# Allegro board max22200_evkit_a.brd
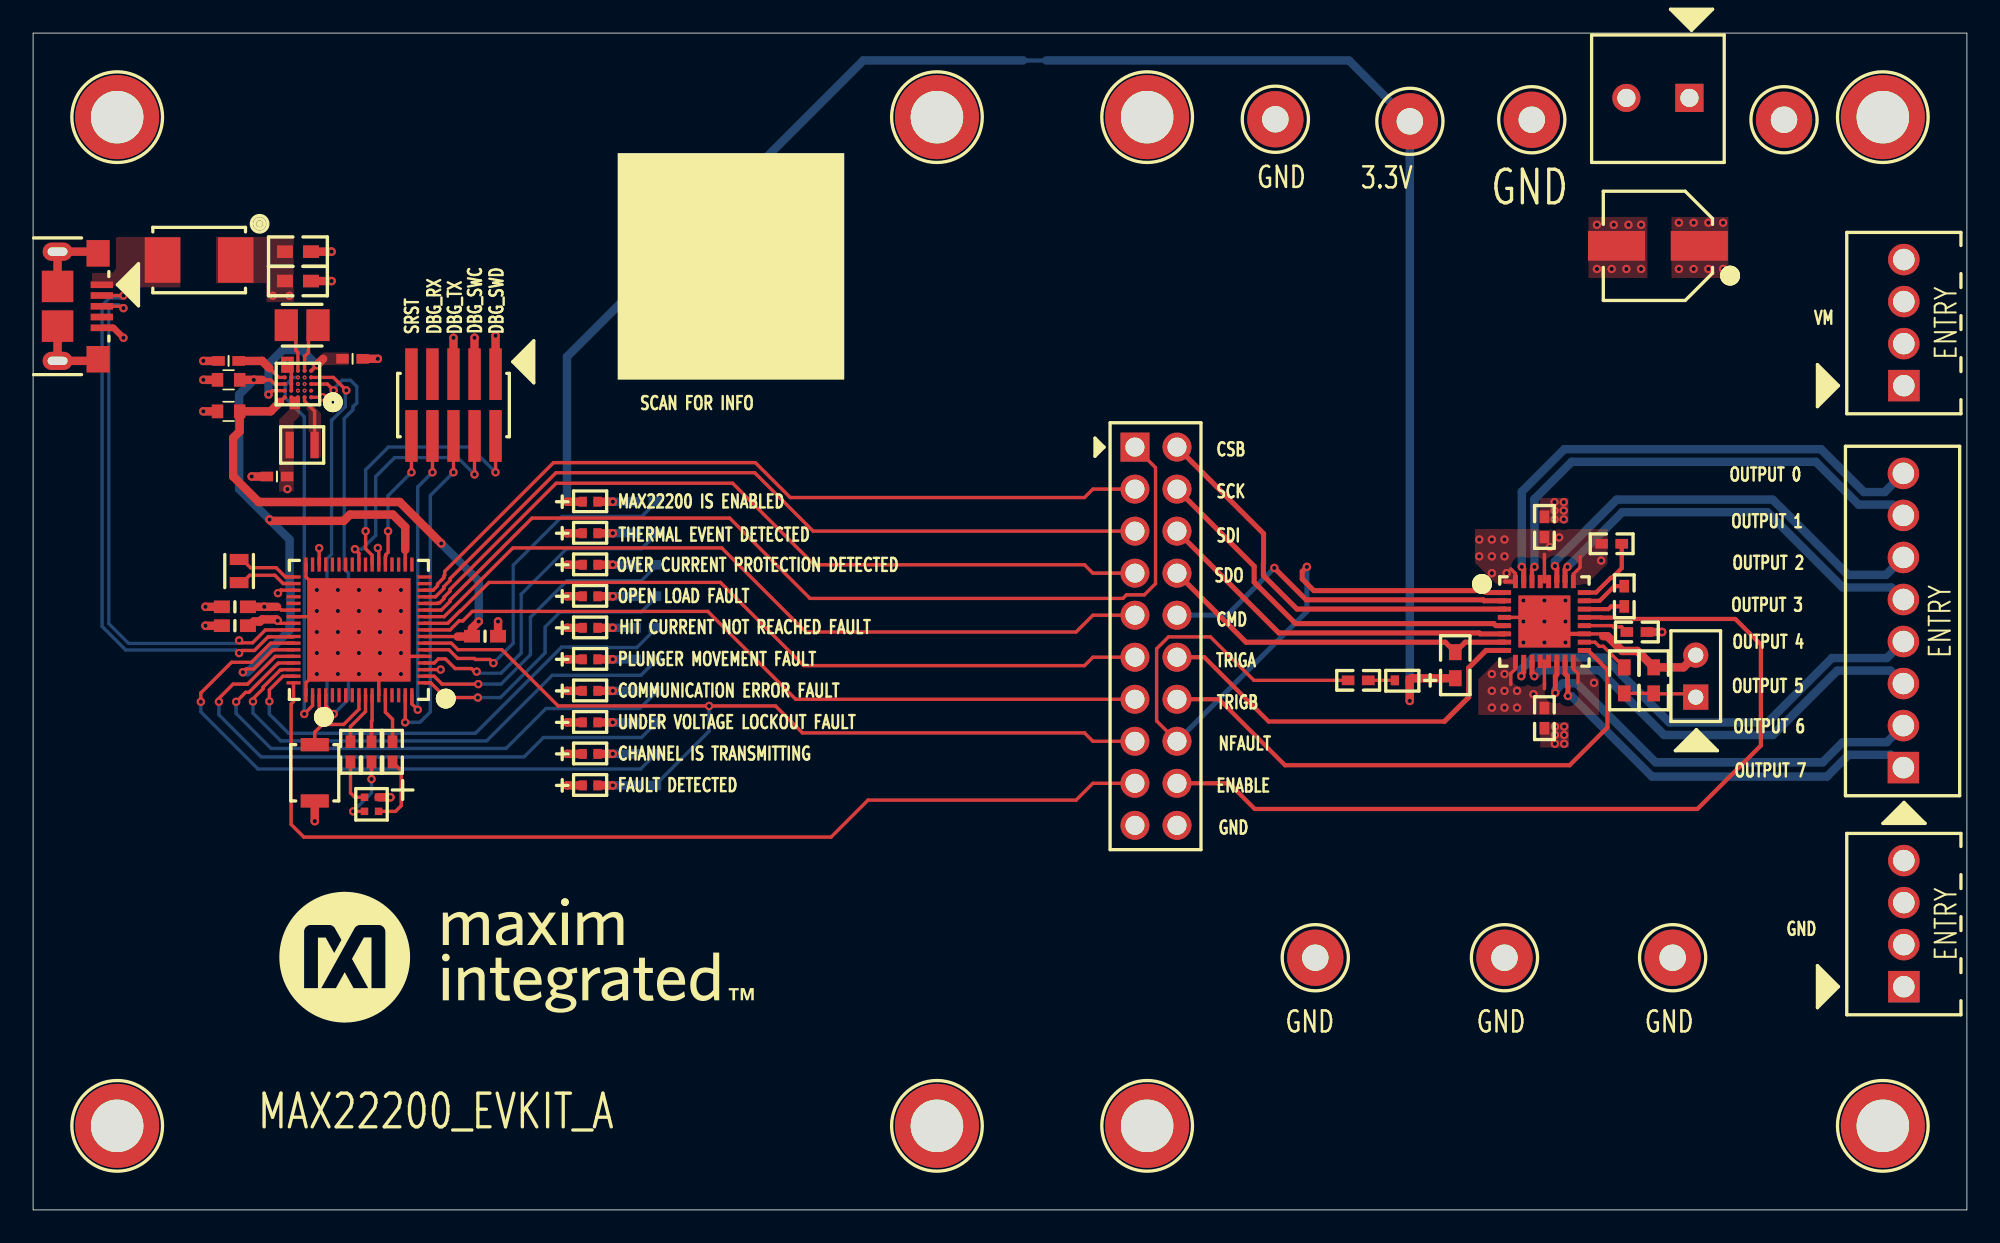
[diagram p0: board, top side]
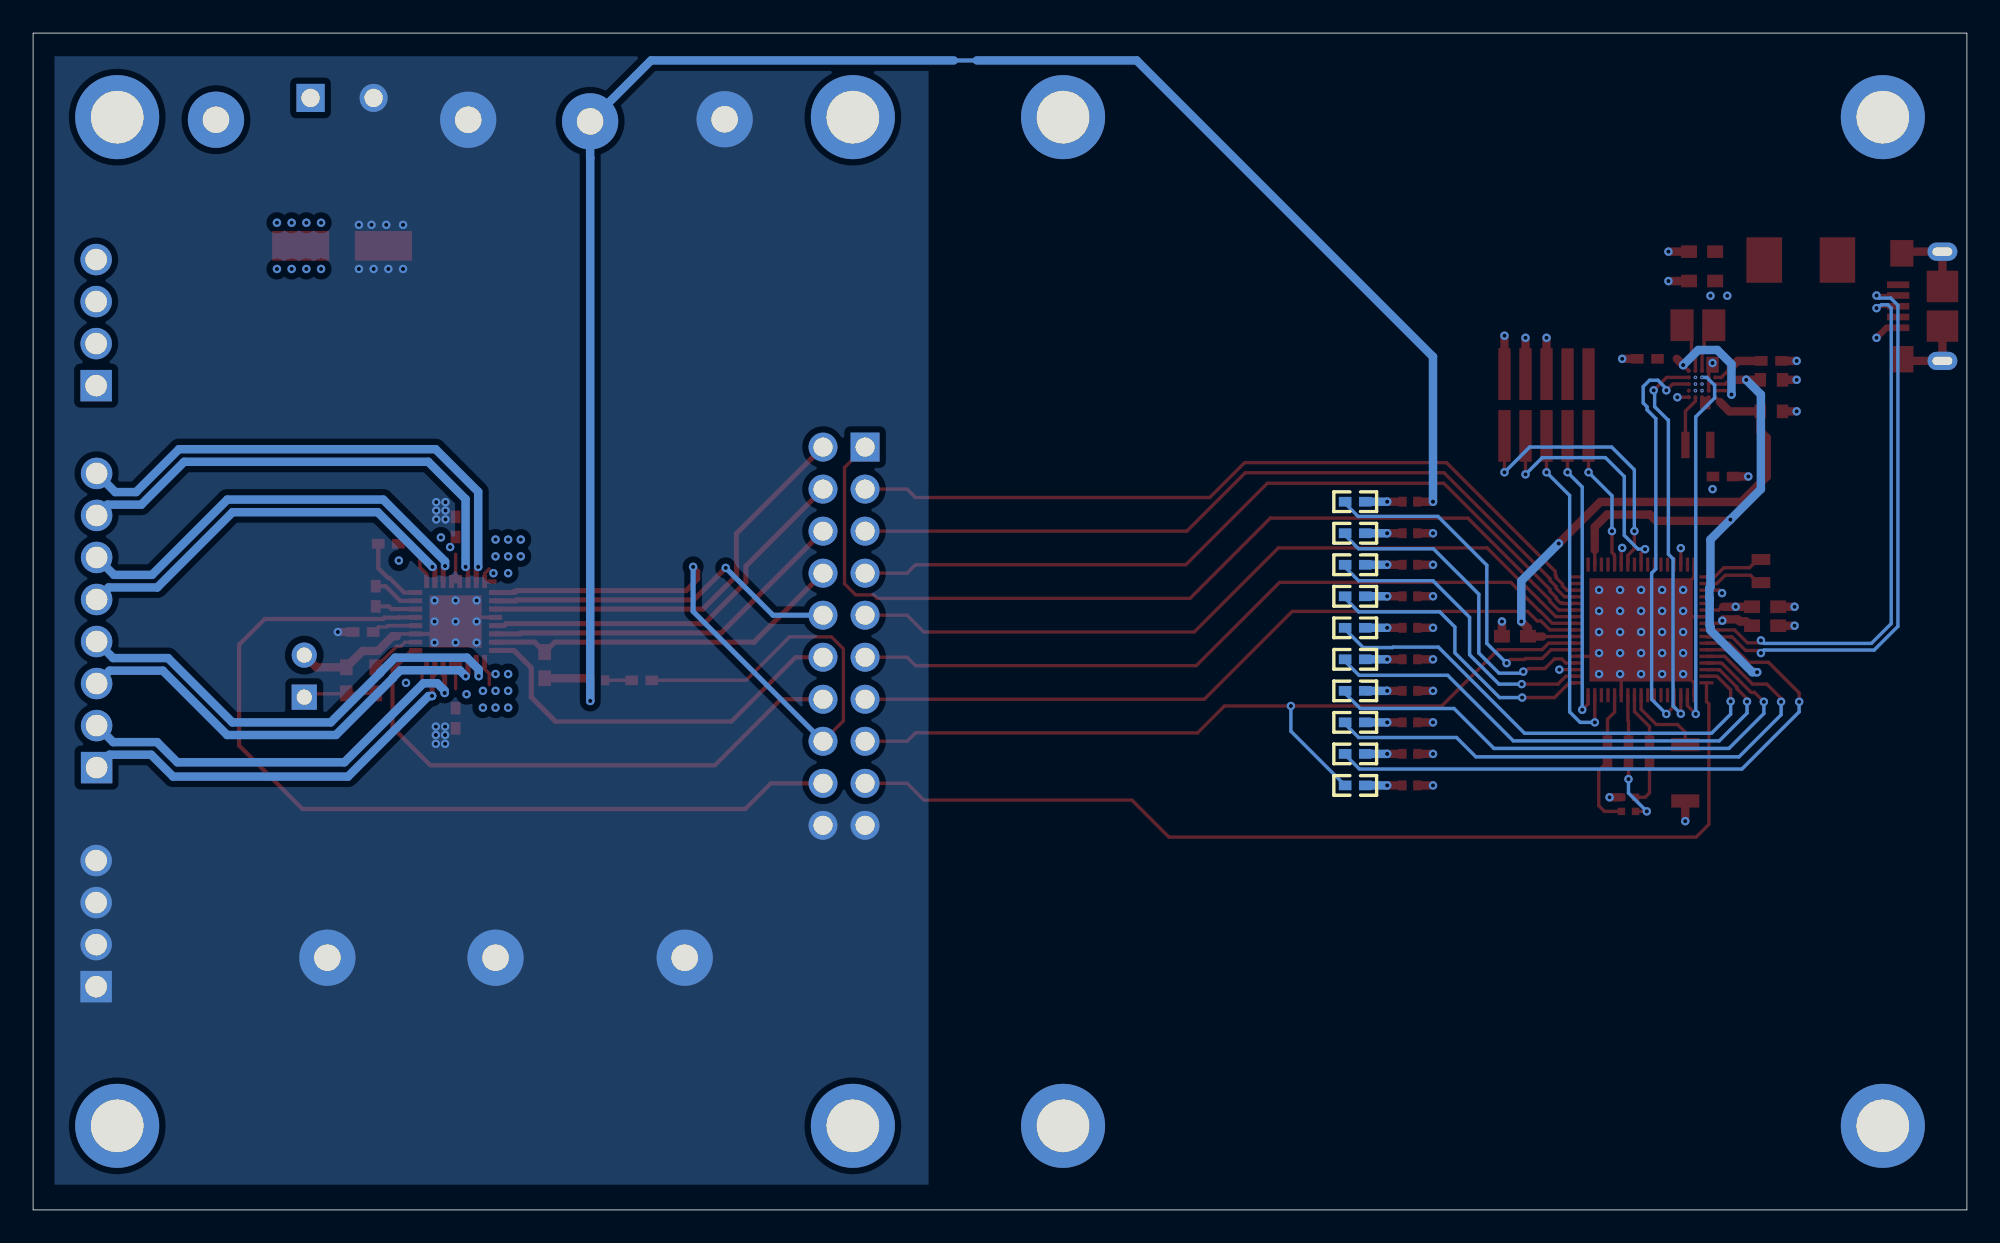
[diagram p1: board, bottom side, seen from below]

Outline 116.84 x 71.12 mm; copper layers: TOP, GND2, PWR3, BOTTOM. Coordinates in mm from the lower left corner of the outline.
Outline path: 0,71.12 116.84,71.12 116.84,0 0,0 0,71.12

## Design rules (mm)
constraint set DEFAULT: min track width 0.203
net group DIFF_USB: nets USB_DM USB_DP
net group PWR_DRIVER: nets UNNAMED_1_EKMAX22200_I141_10 UNNAMED_1_EKMAX22200_I141_11 UNNAMED_1_EKMAX22200_I141_14 UNNAMED_1_EKMAX22200_I141_15 UNNAMED_1_EKMAX22200_I141_26 UNNAMED_1_EKMAX22200_I141_27 UNNAMED_1_EKMAX22200_I141_30 UNNAMED_1_EKMAX22200_I141_31 VDD

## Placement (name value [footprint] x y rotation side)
C1  1UF  [0603#2]  16 56.13 180 top
C2  10UF  [0603#2]  16 57.91 180 top
C3  22UF  [0402]  19.3 51.44 0 top
C4  22UF  [0402]  14.73 44.32 0 top
C5  10UF  [0603]  11.81 48.26 0 top
C6  1UF  [0603]  11.81 50.16 0 top
C7  0.1UF  [0402]  11.81 51.31 180 top
C8  1UF  [0603#2]  12.19 35.31 0 top
C9  1UF  [0603#2]  27.3 34.67 180 top
C10  1UF  [0603#2]  12.19 36.45 0 top
C17  0.22UF  [0402]  91.31 41.27 90 top
C18  0.22UF  [0402]  91.31 29.72 270 top
C19  2.2UF  [0402]  96.9 34.92 180 top
C20  1UF  [0402]  95.38 40.26 180 top
C21  0.022UF  [0402]  96.14 37.08 90 top
C23  22UF  [CAPAE660X580M]  98.17 58.26 180 top
D1  SML-P11MTT86  [LED_0402]  33.66 42.8 180 top
D2  SML-P11UTT86  [LED_0402]  33.66 40.89 180 top
D3  SML-P11UTT86  [LED_0402]  33.66 38.99 180 top
D4  SML-P11UTT86  [LED_0402]  33.66 37.08 180 top
D5  SML-P11UTT86  [LED_0402]  33.66 35.18 180 top
D6  SML-P11UTT86  [LED_0402]  33.66 33.27 180 top
D7  SML-P11UTT86  [LED_0402]  33.66 31.37 180 top
D8  SML-P11UTT86  [LED_0402]  33.66 29.46 180 top
D9  SML-P11MTT86  [LED_0402]  33.66 27.56 180 top
D10  SML-P11UTT86  [LED_0402]  33.66 25.65 180 top
D11  VS-10BQ040-M3  [DIOM5436X265M]  10.03 57.4 180 top
D12  SML-LX0404SIUPGUSB  [LED_LX0404]  20.45 24.51 0 top
D13  SML-P11UTT86  [LED_0402]  82.73 32 0 top
J1  10118193-0001LF  [FCI_10118193-0001LF]  1.48 54.61 270 top
J2  FTS-105-01-L-DV  [EK_SAMTEC_FTS-105-01-L-DV]  25.4 48.64 180 top
J3  N/A  [KEYS_5010]  83.19 65.79 0 top
J4  1727010  [PNIX_1727010]  100.08 67.2 180 top
J6  N/A  [KEYS_5010]  105.79 65.88 0 top
J7  N/A  [KEYS_5011]  90.55 65.88 0 top
J8  N/A  [KEYS_5011]  75.06 65.91 0 top
J9  OSTVN04A150  [OSTI_OSTVN04A1X0]  113.03 49.81 90 top
J10  OSTVN04A150  [OSTI_OSTVN04A1X0]  113.03 13.49 90 top
J11  PEC10DAAN  [SULLINS_PXC10DAAN]  66.57 46.1 270 top
J12  OSTVN08A150  [OST_OSTVN08A1X0]  113 26.73 90 top
J13  N/A  [KEYS_5011]  77.47 15.24 0 top
J14  N/A  [KEYS_5011]  88.9 15.24 0 top
J15  N/A  [KEYS_5011]  99.06 15.24 0 top
J16  PBC02SAAN  [EK_SULLINS_PXC02SAAN]  100.46 30.99 90 top
L1  2.2UH  [IND_VLS-HBX-1]  16.26 46.23 180 top
L2  4.7UH  [INDC2016X120M]  16.26 53.47 180 top
NOREF  -  []  35.32 50.18 0 top
NOREF#2  -  [unnamed#2]  111.76 66.04 0 top
NOREF#3  -  []  58.36 100.35 0 top
NOREF#4  -  []  123.19 141.32 0 top
NOREF#5  -  []  0 8.89 90 top
NOREF#6  -  []  91.12 143.29 0 top
NOREF#7  -  []  2.35 16.47 0 top
NOREF#8  -  []  0 71.12 0 top
NOREF#9  -  []  18.85 15.17 0 top
NOREF#10  -  []  161.29 25.4 0 top
NOREF#11  -  [unnamed#2]  67.31 5.08 0 top
NOREF#12  -  []  51.73 10.79 0 top
NOREF#13  -  []  12.7 -12.7 0 top
NOREF#14  -  [unnamed#2]  54.61 66.04 0 top
NOREF#15  -  [unnamed#2]  67.31 66.04 0 top
NOREF#16  -  [unnamed#2]  54.61 5.08 0 top
NOREF#17  -  [unnamed#2]  5.08 66.04 0 top
NOREF#18  -  []  93.34 85.09 0 top
NOREF#19  -  [unnamed#2]  111.76 5.08 0 top
NOREF#20  -  [unnamed#2]  5.08 5.08 0 top
R1  3.09K  [0402]  21.72 27.69 270 top
R2  1.1K  [0402]  20.45 27.69 270 top
R3  1.4K  [0402]  19.18 27.69 270 top
R5  1.5K  [0402]  36.96 42.8 0 bottom
R6  1.4K  [0402]  36.96 40.89 0 bottom
R7  1.4K  [0402]  36.96 38.99 0 bottom
R8  1.4K  [0402]  36.96 37.08 0 bottom
R9  1.4K  [0402]  36.96 35.18 0 bottom
R10  1.4K  [0402]  36.96 33.27 0 bottom
R11  1.4K  [0402]  36.96 31.37 0 bottom
R12  1.4K  [0402]  36.96 29.46 0 bottom
R13  1.5K  [0402]  36.96 27.56 0 bottom
R14  1K  [0603#2]  85.93 32.92 270 top
R15  1.4K  [0402]  36.96 25.65 0 bottom
R17  15K  [0603#2]  96.14 32 90 top
R18  15K  [0603#2]  97.92 32 270 top
R20  1.4K  [0402]  80.06 32 180 top
SW1  B3U-1000P  [SW_B3U-1000PX]  17.02 26.42 270 top
U1  MAX22200  [MAXIM_90-0013]  91.31 35.56 0 top
U2  MAX32625ITK+  [MAXIM_90-0354]  19.68 35.05 180 top
U3  MAX14750AEWA+  [MAXIM_21-0788]  16 49.91 180 top
X1  32.768KHZ  [XTALDFN2_200X120X60L50X100M]  12.45 38.61 90 top

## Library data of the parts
C1 C6 C8-C10 = CAP_NP: alternate symbols: 0603_NOSILK,CAPC1608X90L,CAP0603-NOT_FOR_TEST; part number: CAP_NP_0603CAP-0603,1UF,20-0001U-P6
C2 C5 = CAP_NP: alternate symbols: CAPC1608X90L; part number: CAP_NP_0603CAP-0603,10UF,20-0010U-16
C3 C4 = CAP_NP: alternate symbols: 0402_NOSILK,CAPC1005X50L,CAP0402-NOT_FOR_TEST; part number: CAP_NP_0402CAP-0402,22UF,20-0022U-CA54
C7 = CAP_NP: alternate symbols: 0402_NOSILK,CAPC1005X50L; part number: CAP_NP_0402CAP-0402,0.1UF,20-000U1-16B
C17 C18 = CAP_NP: alternate symbols: 0402_NOSILK,CAPC1005X50L; part number: CAP_NP_0402CAP-0402,0.22UF,20-00U22-A0Z
C19 = CAP_NP: alternate symbols: 0402_NOSILK,CAPC1005X50L; part number: CAP_NP_0402CAP-0402,2.2UF,20-002U2-A44
C20 = CAP_NP: alternate symbols: 0402_NOSILK,CAPC1005X50L,CAP0402-NOT_FOR_TEST; part number: CAP_NP_0402CAP-0402,1UF,20-0001U-B8
C21 = CAP_NP: alternate symbols: 0402_NOSILK,CAPC1005X50L; part number: CAP_NP_0402CAP-0402,0.022UF,20-0U022-B60
C23 = CAP_POL: part number: CAP_POL_CASED-CAPAE660X580M,22UF,20-0022U-DA55
D1 D9 = LED: part number: LED_LED_0402-LED_0402,SML-P11MTT86,30-SMLP11MTT86-00
D2-D8 D10 D13 = LED: alternate symbols: LEDC1006X25L; part number: LED_LED_0402-LED_0402,SML-P11UTT86,30-SMLP11UTT86-00
D11 = DIO_SCHOTTKY: part number: DIO_SCHOTTKY_DO-214AA-DIOM5436X265M,VS-10BQ040-M3,30-VS10BQ040-00
D12 = LED_4P: alternate symbols: OSCCC100X100X30L; part number: LED_4P_LX0404-LED_LX0404,SML-LX0404SIUPGUSB,30-SMLLX0404SIUPGUSB-00
J1 = 10118193-0001LF: part number: 10118193-0001LF_SMD-FCI_10118193-0001LF,10118193-0001LF,01-101181930001LF5P-26
J2 = EK_HEADER_5P_X_2R: part number: EK_HEADER_5P_X_2R_SMD-EK_SAMTEC_FTS-105-01-L-DV,FTS-105-01-L-DV,01-FTS10501LDV10P-21
J3 J6 = TP: alternate symbols: TP_C340H160L; part number: TP_TP-KEYS_5010,N/A,02-TPMINI5010-00
J4 = HEADER_2P: part number: HEADER_2P_TERM_BLK_2P-PNIX_1727010,1727010,01-17270102P-25
J7 J8 J13-J15 = TP: alternate symbols: TP_C340H160L; part number: TP_TP-KEYS_5011,N/A,02-TPMINI5011-00
J9 J10 = HEADER_4P: part number: HEADER_4P_TERM_BLK-OSTI_OSTVN04A1X0,OSTVN04A150,EH111000002457
J11 = HEADER_10P_X_2R: part number: HEADER_10P_X_2R_TH-SULLINS_PXC10DAAN,PEC10DAAN,01-PEC10DAAN20P-21
J12 = HEADER_8P: part number: HEADER_8P_TERM_BLK-OST_OSTVN08A1X0,OSTVN08A150,01-OSTVN08A1508P-25
J16 = EK_HEADER_2P: part number: EK_HEADER_2P_TH-EK_SULLINS_PXC02SAAN,PBC02SAAN,01-PBC02SAAN2P-21
L1 = INDUCT: part number: INDUCT_IND_VLS-HBX-1-IND_VLS-HBX-1,2.2UH,50-002U2-0MQ
L2 = INDUCT: alternate symbols: INDC2016X100L; part number: INDUCT_2016-INDC2016X120M,4.7UH,50-004U7-OFA
R1 = RES: alternate symbols: (0402_NOSILK,RESC1005X50L); part number: RES_0402RES-0402,3.09K,80-03K09-23
R2 = RES: alternate symbols: (0402_NOSILK,RESC1005X50L); part number: RES_0402RES-0402,1.1K,80-001K1-23
R3 R6-R12 R15 R20 = RES: alternate symbols: (0402_NOSILK,RESC1005X50L); part number: RES_0402RES-0402,1.4K,80-001K4-23
R5 R13 = RES: alternate symbols: (0402_NOSILK,RESC1005X50L); part number: RES_0402RES-0402,1.5K,80-001K5-23G
R14 = RES: alternate symbols: 0603_NOSILK,RESC1608X90L; part number: RES_0603RES-0603,1K,80-0001K-53
R17 R18 = RES: alternate symbols: 0603_NOSILK,RESC1608X90L; part number: RES_0603RES-0603,15K,80-0015K-24
SW1 = B3U-1000PX: part number: B3U-1000PX_SMD-SW_B3U-1000PX,B3U-1000P,11-B3U1000P-00
U1 = EK_MAX22200: part number: EK_MAX22200_SPLIT_TQFN32-EP-MAXIM_90-0013,MAX22200,N/A
U2 = MAX32625: part number: MAX32625_TQFN68-EP-MAXIM_90-0354,MAX32625ITK+,10-MAX32625ITK-T
U3 = MAX14750: part number: MAX14750_WLP25-MAXIM_21-0788,MAX14750AEWA+,10-MAX14750AEWA-W
X1 = XTAL: part number: XTAL_ECX-12-XTALDFN2_200X120X60L50X100M,32.768KHZ,60-32K76-0FC

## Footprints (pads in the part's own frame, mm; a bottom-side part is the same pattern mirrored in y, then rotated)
0402
  rect 0.762x0.584 smd: 1(-0.61,0) 2(0.61,0)
0603
  rect 0.69x0.83 smd: 1(-0.67,0) 2(0.67,0)
0603#2
  rect 0.965x0.762 smd: 1(-0.787,0) 2(0.787,0)
CAPAE660X580M
  rect 3.45x1.8 smd: 1(-2.5,0) 2(2.5,0)
DIOM5436X265M
  rect 2.15x2.75 smd: A(2.21,0) C(-2.21,0)
EK_SAMTEC_FTS-105-01-L-DV
  rect 0.75x3.125 smd: 1(-2.54,-1.867) 2(-1.27,-1.867) 3(0,-1.867) 4(1.27,-1.867) 5(2.54,-1.867) 6(-2.54,1.867) 7(-1.27,1.867) 8(0,1.867) 9(1.27,1.867) 10(2.54,1.867)
EK_SULLINS_PXC02SAAN
  rect 1.524x1.524 hole 0.914: 1(0,0)
  round 1.524 hole 0.914: 2(2.54,0)
FCI_10118193-0001LF
  rect 0.4x1.35 smd: 1(-1.3,2.675) 2(-0.65,2.675) 3(0,2.675) 4(0.65,2.675) 5(1.3,2.675)
  rect 1.6x1.4 smd: 6(-3.2,2.45) 7(3.2,2.45)
  rect 1.9x1.9 smd: 8(-1.2,0) 9(1.2,0)
  oval 1.1x1.8 hole 0.5x1.2: 10(-3.3,0) 11(3.3,0)
IND_VLS-HBX-1
  rect 0.5x1.6 smd: 1(-0.75,0) 2(0.75,0)
INDC2016X120M
  rect 1.4x1.92 smd: 1(-0.96,0) 2(0.96,0)
KEYS_5010
  round 3.4 hole 1.6: 1(0,0)
KEYS_5011
  round 3.4 hole 1.6: 1(0,0)
LED_0402
  rect 0.5x0.6 smd: A(0.45,0) C(-0.45,0)
LED_LX0404
  rect 0.45x0.45 smd: 1(0.425,0.425) 2(0.425,-0.425) 3(-0.425,-0.425) 4(-0.425,0.425)
MAXIM_21-0788
  round 0.25 smd: A1(-0.8,0.8) A2(-0.4,0.8) A3(0,0.8) A4(0.4,0.8) A5(0.8,0.8) B1(-0.8,0.4) B2(-0.4,0.4) B3(0,0.4) B4(0.4,0.4) B5(0.8,0.4) C1(-0.8,0) C2(-0.4,0) C3(0,0) C4(0.4,0) C5(0.8,0) D1(-0.8,-0.4) D2(-0.4,-0.4) D3(0,-0.4) D4(0.4,-0.4) D5(0.8,-0.4) E1(-0.8,-0.8) E2(-0.4,-0.8) E3(0,-0.8) E4(0.4,-0.8) E5(0.8,-0.8)
MAXIM_90-0013
  rect 0.8x0.3 smd: 1(-2.415,1.75) 2(-2.415,1.25) 3(-2.415,0.75) 4(-2.415,0.25) 5(-2.415,-0.25) 6(-2.415,-0.75) 7(-2.415,-1.25) 8(-2.415,-1.75) 17(2.415,-1.75) 18(2.415,-1.25) 19(2.415,-0.75) 20(2.415,-0.25) 21(2.415,0.25) 22(2.415,0.75) 23(2.415,1.25) 24(2.415,1.75)
  rect 0.3x0.8 smd: 9(-1.75,-2.415) 10(-1.25,-2.415) 11(-0.75,-2.415) 12(-0.25,-2.415) 13(0.25,-2.415) 14(0.75,-2.415) 15(1.25,-2.415) 16(1.75,-2.415) 25(1.75,2.415) 26(1.25,2.415) 27(0.75,2.415) 28(0.25,2.415) 29(-0.25,2.415) 30(-0.75,2.415) 31(-1.25,2.415) 32(-1.75,2.415)
  rect 3.15x3.15 smd: 33(0,0)
MAXIM_90-0354
  rect 0.85x0.2 smd: 1(-3.95,3.2) 2(-3.95,2.8) 3(-3.95,2.4) 4(-3.95,2) 5(-3.95,1.6) 6(-3.95,1.2) 7(-3.95,0.8) 8(-3.95,0.4) 9(-3.95,0) 10(-3.95,-0.4) 11(-3.95,-0.8) 12(-3.95,-1.2) 13(-3.95,-1.6) 14(-3.95,-2) 15(-3.95,-2.4) 16(-3.95,-2.8) 17(-3.95,-3.2) 35(3.95,-3.2) 36(3.95,-2.8) 37(3.95,-2.4) 38(3.95,-2) 39(3.95,-1.6) 40(3.95,-1.2) 41(3.95,-0.8) 42(3.95,-0.4) 43(3.95,0) 44(3.95,0.4) 45(3.95,0.8) 46(3.95,1.2) 47(3.95,1.6) 48(3.95,2) 49(3.95,2.4) 50(3.95,2.8) 51(3.95,3.2)
  rect 0.2x0.85 smd: 18(-3.2,-3.95) 19(-2.8,-3.95) 20(-2.4,-3.95) 21(-2,-3.95) 22(-1.6,-3.95) 23(-1.2,-3.95) 24(-0.8,-3.95) 25(-0.4,-3.95) 26(0,-3.95) 27(0.4,-3.95) 28(0.8,-3.95) 29(1.2,-3.95) 30(1.6,-3.95) 31(2,-3.95) 32(2.4,-3.95) 33(2.8,-3.95) 34(3.2,-3.95) 52(3.2,3.95) 53(2.8,3.95) 54(2.4,3.95) 55(2,3.95) 56(1.6,3.95) 57(1.2,3.95) 58(0.8,3.95) 59(0.4,3.95) 60(0,3.95) 61(-0.4,3.95) 62(-0.8,3.95) 63(-1.2,3.95) 64(-1.6,3.95) 65(-2,3.95) 66(-2.4,3.95) 67(-2.8,3.95) 68(-3.2,3.95)
  rect 6.25x6.25 smd: 69(0,0)
OST_OSTVN08A1X0
  rect 1.9x1.9 hole 1.3: 1(0,0)
  round 1.9 hole 1.3: 2(2.54,0) 3(5.08,0) 4(7.62,0) 5(10.16,0) 6(12.7,0) 7(15.24,0) 8(17.78,0)
OSTI_OSTVN04A1X0
  rect 1.9x1.9 hole 1.3: 1(0,0)
  round 1.9 hole 1.3: 2(2.54,0) 3(5.08,0) 4(7.62,0)
PNIX_1727010
  rect 1.7x1.7 hole 1.1: 1(0,0)
  round 1.7 hole 1.1: 2(3.81,0)
SULLINS_PXC10DAAN
  rect 1.75x1.75 hole 1.15: 1(0,0)
  round 1.75 hole 1.15: 2(0,2.54) 3(2.54,0) 4(2.54,2.54) 5(5.08,0) 6(5.08,2.54) 7(7.62,0) 8(7.62,2.54) 9(10.16,0) 10(10.16,2.54) 11(12.7,0) 12(12.7,2.54) 13(15.24,0) 14(15.24,2.54) 15(17.78,0) 16(17.78,2.54) 17(20.32,0) 18(20.32,2.54) 19(22.86,0) 20(22.86,2.54)
SW_B3U-1000PX
  rect 0.8x1.7 smd: 1(-1.7,0) 2(1.7,0)
unnamed#2
  round 5.08 hole 3.175: (0,0)
XTALDFN2_200X120X60L50X100M
  rect 0.67x1.13 smd: 1(-0.7,0) 2(0.7,0)

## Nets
1.8V: C4.2 C8.2 J2.1 L1.2 U2.3 U2.23 U2.32 U2.37 U2.42 U3.A3 U3.A4
3.3V: C3.1 C10.2 D1.A D2.A D3.A D4.A D5.A D6.A D7.A D8.A D9.A D10.A D12.1 D13.A J3.1(TP1) R14.2 U2.40 U3.B5 U3.E1
3V3_IOH_EN: U2.53 U3.D3
GND_SIGNAL: C1.1 C2.1 C3.2 C4.1 C5.1 C6.1 C7.2 C8.1 C9.1 C10.1 C17.2 C18.2 C19.1 C23.2(B) J1.5 J1.6 J1.7 J1.8 J1.9 J1.10 J1.11 J2.2 J2.3 J4.2 J7.1(TP1) J8.1(TP1) J10.1 J10.2 J10.3 J10.4 J11.19 J11.20 J13.1(TP1) J14.1(TP1) J15.1(TP1) J16.2 R18.1 SW1.2 U1.4 U1.19 U1.33 U2.5 U2.34 U2.41 U2.52 U2.63(VSS_5) U2.69 U3.B2 U3.B3 U3.C2 U3.C3 U3.D2
VDD: C5.2 C9.2 U2.8 U3.A5
DBG_RX: J2.9 U2.68
DBG_SWC: J2.7 U2.26
DBG_SWD: J2.6 U2.24
DBG_TX: J2.8 U2.67
DUT_CMD: J11.10 U1.2
DUT_CSB: J11.2 U1.3
DUT_ENABLE: J11.18 U1.21
DUT_NFAULT: J11.16 R20.2 U1.1
DUT_SCK: J11.4 U1.5
DUT_SDI: J11.6 U1.6
DUT_SDO: J11.8 R14.1 U1.7
DUT_TRIGA: J11.12 U1.8
DUT_TRIGB: J11.14 U1.17
FAULT_LED1: R5.2 U2.6
FAULT_LED2: R6.2 U2.4
FAULT_LED3: R7.2 U2.2
FAULT_LED4: R8.2 U2.1
FAULT_LED5: R9.2 U2.50
FAULT_LED6: R10.2 U2.49
FAULT_LED7: R11.2 U2.48
FAULT_LED8: R12.2 U2.47
FAULT_LED9: R13.2 U2.45
MCU_CMD: J11.9 U2.11
MCU_CSB: J11.1 U2.12
MCU_ENABLE: J11.17 U2.51
MCU_NFAULT: J11.15 R15.2 U2.7
MCU_SCK: J11.3 U2.15
MCU_SDI: J11.5 U2.14
MCU_SDO: J11.7 U2.13
MCU_TRIGA: J11.11 U2.10
MCU_TRIGB: J11.13 U2.9
PMIC_SCL: U2.54 U3.D1
PMIC_SDA: U2.55 U3.C1
SRST: J2.10 U2.22
SWOUT: C6.2 U2.19 U2.46 U3.C5
UNNAMED_1_CAPNP_I58_1: C21.1 U1.22
UNNAMED_1_CAPNP_I58_2: C21.2 U1.23
UNNAMED_1_CAPNP_I62_2: C19.2 U1.20
UNNAMED_1_CAPNP_I64_1: C20.1 U1.24
UNNAMED_1_EKHEADER2P_I105_1: J16.1 R17.1 R18.2
UNNAMED_1_EKMAX22200_I140_18: R17.2 U1.18
UNNAMED_1_EKMAX22200_I141_10: J12.4 U1.10
UNNAMED_1_EKMAX22200_I141_11: J12.3 U1.11
UNNAMED_1_EKMAX22200_I141_14: J12.2 U1.14
UNNAMED_1_EKMAX22200_I141_15: J12.1 U1.15
UNNAMED_1_EKMAX22200_I141_26: J12.5 U1.26
UNNAMED_1_EKMAX22200_I141_27: J12.6 U1.27
UNNAMED_1_EKMAX22200_I141_30: J12.7 U1.30
UNNAMED_1_EKMAX22200_I141_31: J12.8 U1.31
UNNAMED_1_LED_I106_B: D13.C(B) R20.1
UNNAMED_4_10118193-0001LF_I7_1: D11.A J1.1
UNNAMED_4_B3U-1000PX_I48_1: SW1.1 U2.60
UNNAMED_4_CAPNP_I15_2: C1.2 C2.2 D11.C(K) U3.A1 U3.B4(VCC) U3.C4 U3.D4 U3.E4 U3.E5
UNNAMED_4_CAPNP_I35_1: C7.1 U3.D5
UNNAMED_4_INDUCT_I43_1: L2.1 U3.E2
UNNAMED_4_INDUCT_I43_2: L2.2 U3.E3
UNNAMED_4_INDUCT_I44_1: L1.1 U3.A2
UNNAMED_4_LED4P_I4_KB: D12.3 R2.2
UNNAMED_4_LED4P_I4_KG: D12.4 R3.2
UNNAMED_4_LED4P_I4_KR: D12.2(KR) R1.2
UNNAMED_4_LED_I50_B: D1.C(B) R5.1
UNNAMED_4_LED_I52_B: D2.C(B) R6.1
UNNAMED_4_LED_I55_B: D3.C(B) R7.1
UNNAMED_4_LED_I57_B: D4.C(B) R8.1
UNNAMED_4_LED_I59_B: D5.C(B) R9.1
UNNAMED_4_LED_I61_B: D6.C(B) R10.1
UNNAMED_4_LED_I63_B: D7.C(B) R11.1
UNNAMED_4_LED_I65_B: D8.C(B) R12.1
UNNAMED_4_LED_I66_B: D9.C(B) R13.1
UNNAMED_4_LED_I70_B: D10.C(B) R15.1
UNNAMED_4_MAX32625_I78_32KIN: U2.35 X1.2
UNNAMED_4_MAX32625_I78_32KOUT: U2.36 X1.1
UNNAMED_4_MAX32625_I78_P2: R1.1 U2.64
UNNAMED_4_MAX32625_I78_P2_1: R2.1 U2.62
UNNAMED_4_MAX32625_I78_P2_2: R3.1 U2.61
USB_DM: J1.2 U2.44
USB_DP: J1.3 U2.43
VM: C17.1 C18.1 C20.2 C23.1 J4.1 J6.1(TP1) J9.1 J9.2 J9.3 J9.4 U1.9 U1.12 U1.13 U1.16 U1.25 U1.28 U1.29 U1.32

Pads without a net: J1 4; J2 4 5; U2 16 17 18 20 21 25 27 28 29 30 31 33 38 39 56 57 58 59 65 66; U3 B1

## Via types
v1: diameter 0.508, hole 0.254, TOP to BOTTOM, 180 vias
v2: diameter 0.203, hole 0.102, TOP to BOTTOM, 6 vias

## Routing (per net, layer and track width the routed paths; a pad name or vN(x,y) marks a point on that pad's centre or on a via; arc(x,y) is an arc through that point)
1.8V: length 9.4
  TOP w0.203: U2.23 20.88,39.95 v1(20.83,40) ; 23.64,32.65 v1(24.63,32.65) ; U2.32 v1(17.28,39.99) ; v1(14.78,35.61) 14.94,35.45 15.73,35.45 U2.42 ; 14.97,37.45 15.73,37.45 U2.37
  TOP w0.254: 14.97,37.45 v1(14.8,37.27)
  TOP w0.508: J2.1 v1(27.94,52.83) ; v1(14.78,35.61) 14.7,35.69 13.84,35.69 13.73,35.58 13.69,35.58 13.67,35.56 13.34,35.56 13.08,35.31 C8.2
  vias: v1(15.37,43.56)
3.3V: length 128.3
  TOP w0.203: 14.34,49.4 14.46,49.51 15.2,49.51 U3.B5 ; 14.73,36.45 14.79,36.45 14.99,36.25 15.73,36.25 U2.40
  TOP w0.229: 14.34,49.4 v1(14.22,49.28) ; v1(17.14,51.05) U3.E1
  TOP w0.508: D3.A v1(32.26,38.99) ; C10.2 v1(13.97,36.45) 14.73,36.45 ; D5.A v1(32.26,35.18) ; v1(83.18,30.76) D13.A 83.3,32.13 R14.2 ; D2.A v1(32.26,40.89) ; D8.A v1(32.26,29.46) ; D7.A v1(32.26,31.37) ; D10.A v1(32.26,25.65) ; D4.A v1(32.26,37.08) ; D12.1 v1(21.59,24.94) ; D1.A v1(32.26,42.8) ; v1(17.14,51.05) 17.53,51.44 ; D6.A v1(32.26,33.27) ; D9.A v1(32.26,27.56)
  BOTTOM w0.254: 59.82,69.47 61.21,69.47
  BOTTOM w0.508: v1(83.18,30.76) 83.18,63.57 83.19,63.58 J3.1 79.5,69.47 61.21,69.47 ; 59.82,69.47 50.16,69.47 32.26,51.56 v1(32.26,42.8) ; v1(14.22,49.28) 14.22,51.12 15.08,51.97 16.23,51.97 v1(17.14,51.05)
3V3_IOH_EN: length 22.6
  TOP w0.203: v1(16.38,29.97) 16.88,30.47 16.88,31.1 U2.53
  BOTTOM w0.203: v2(16,50.31) 15.72,50.31 15.24,49.84 15.24,49.07 16.38,47.93 v1(16.38,29.97)
GND_SIGNAL: length 58.8
  TOP w0.203: 20.88,33.85 U2.69 ; 20.88,33.85 U2.63 ; 20.88,33.85 21.28,33.45 U2.5 23.64,33.45 ; U2.69 16.49,31.85 16.49,31.1 U2.52 ; U2.69 18.88,35.85 ; U2.34 16.49,39 16.49,38.25 18.88,35.85 ; 94.87,34.67 94.73,34.81 U1.19 ; 18.88,35.85 U2.41 ; U1.4 89.84,35.81 90.04,35.61 v1(90.04,35.56)
  TOP w0.254: v1(92.58,34.29) 92.58,34.56 92.84,34.81 U1.19
  TOP w0.381: v1(5.46,52.7) 4.86,53.31 J1.5
  TOP w0.508: C1.1 v1(18.03,56.13) ; J1.9 J1.11 3.83,51.31 J1.7 ; C4.1 v1(13.21,44.32) ; C10.1 v1(10.41,36.45) ; C19.1 v1(98.42,34.92) ; J1.6 3.83,57.91 J1.10 J1.8 ; C3.2 v1(20.83,51.44) ; C6.1 v1(10.29,50.16) ; C9.1 v1(28.09,35.56) ; C8.1 v1(10.41,35.31) ; 94.87,34.67 95.12,34.67 96.01,33.78 96.93,33.78 R18.1 99.72,32.79 J16.2 ; J2.2 v1(26.67,52.7) ; C2.1 v1(18.03,57.91) ; J2.3 v1(25.4,52.7) ; C7.2 v1(10.29,51.31) ; SW1.2 v1(17.02,23.5) ; C5.1 v1(10.29,48.26)
  vias: v1(17.14,37.47) v1(17.14,36.2) v1(17.14,34.92) v1(17.14,33.66) v1(17.14,32.39) v1(18.41,37.47) v1(18.41,36.2) v1(18.41,34.92) v1(18.41,33.66) v1(18.41,32.39) v1(19.68,37.47) v1(19.68,36.2) v1(19.68,34.92) v1(19.68,33.66) v1(19.68,32.39) v1(20.95,37.47) v1(20.95,36.2) v1(20.95,34.92) v1(20.95,33.66) v1(20.95,32.39) v1(22.23,37.47) v1(22.23,36.2) v1(22.23,34.92) v1(22.23,33.66) v1(22.23,32.39) v1(90.04,36.83) v1(90.04,34.29) v1(91.31,36.83) v1(91.31,35.56) v1(91.31,34.29) v1(91.92,42.77) v1(91.92,42.27) v1(91.92,41.73) v1(91.95,29.21) v1(91.95,28.7) v1(91.95,28.17) v1(92.48,42.77) v1(92.48,42.27) v1(92.48,41.73) v1(92.51,29.21) v1(92.51,28.7) v1(92.51,28.17) v1(92.58,36.83) v1(92.58,35.56) v1(94.49,59.53) v1(94.49,56.87) v1(95.38,56.87) v1(95.5,59.53) v1(96.27,56.87) v1(96.39,59.53) v1(97.16,59.53) v1(97.16,56.87) v2(16,49.91) v2(16,49.51) v2(16.4,50.31) v2(16.4,49.91) v2(16.4,49.51)
VDD: length 31
  TOP w0.203: 23.64,34.65 25.65,34.65 ; U3.A5 14.92,48.83
  TOP w0.508: 14.92,48.83 14.35,48.26 C5.2 12.48,47.05 12.09,46.66 12.09,44.32 13.63,42.78 22.15,42.78 v1(24.66,40.27) ; v1(26.92,35.56) 26.52,35.15 C9.2 26.5,34.65 25.65,34.65
  BOTTOM w0.508: v1(24.66,40.27) 26.92,38.01 v1(26.92,35.56)
DBG_RX: length 17.9
  TOP w0.203: J2.9 v1(24.13,44.58) ; v1(23.24,30.23) 22.88,30.58 22.88,31.1 U2.68
  BOTTOM w0.203: v1(23.24,30.23) 23.24,43.69 v1(24.13,44.58)
DBG_SWC: length 15.4
  TOP w0.203: J2.7 v1(26.67,44.45) ; U2.26 19.68,39.68 19.45,39.92 v1(19.45,39.93)
  BOTTOM w0.203: v1(26.67,44.45) 25.65,45.47 21.84,45.47 20.7,44.32 20.7,40.77 19.87,39.93 19.46,39.93 19.46,39.93 v1(19.45,39.93)
DBG_SWD: length 17.1
  TOP w0.203: J2.6 v1(27.94,44.58) ; U2.24 20.49,39.56 20.09,39.95 v1(20.09,41.02)
  BOTTOM w0.203: v1(20.09,41.02) 20.09,44.73 21.46,46.1 26.42,46.1 v1(27.94,44.58)
DBG_TX: length 20.7
  TOP w0.203: J2.8 v1(25.4,44.58) ; U2.67 22.49,31.1 22.49,29.47 v1(22.48,29.46)
  BOTTOM w0.203: v1(25.4,44.58) 24,43.18 24,30.1 23.37,29.46 v1(22.48,29.46)
DUT_CMD: length 21.8
  TOP w0.305: U1.2 87.67,36.81 87.61,36.87 76.92,36.87 v1(74.99,38.8)
  BOTTOM w0.305: v1(74.99,38.8) 72.14,35.94 J11.10
DUT_CSB: length 25.3
  TOP w0.305: U1.3 76.36,36.31 74.33,38.34 74.33,39.07 74.35,39.08 74.35,40.87 J11.2
DUT_ENABLE: length 55
  TOP w0.254: U1.21 94.72,35.81 94.74,35.79 95.61,35.79 95.69,35.71 102.84,35.71 104.39,34.16 104.39,28.07 100.56,24.23 73.81,24.23 72.26,25.78 J11.18
DUT_NFAULT: length 46.3
  TOP w0.203: R20.2 73.76,32 71.13,34.63 68.6,34.63 67.88,33.91 67.88,29.55 69.11,28.32
  TOP w0.305: U1.1 87.85,37.31 87.81,37.35 87.68,37.35 87.61,37.43 77.38,37.43 76.68,38.13 76.68,38.58 v1(76.96,38.86)
  BOTTOM w0.305: v1(76.96,38.86) 76.96,36.17 69.11,28.32
DUT_SCK: length 23.8
  TOP w0.305: U1.5 88.38,35.31 88.26,35.43 76.28,35.43 73.77,37.94 73.77,38.9 J11.4
DUT_SDI: length 22.4
  TOP w0.305: J11.6 75.27,34.87 87.38,34.87 87.43,34.81 U1.6
DUT_SDO: length 22
  TOP w0.305: U1.7 86.53,34.31 R14.1 85.32,34.31 73.28,34.31 69.11,38.48
DUT_TRIGA: length 24.2
  TOP w0.254: 85.27,29.51 74.65,29.51 70.76,33.4 J11.12
  TOP w0.305: U1.8 87.78,33.81 86.74,32.77 86.74,30.99 85.27,29.51
DUT_TRIGB: length 34
  TOP w0.254: 69.11,30.86 71.65,30.86 75.64,26.87 92.84,26.87 95.12,29.16 95.12,32.64 93.95,33.81 U1.17
FAULT_LED1: length 21.1
  TOP w0.203: 23.64,33.85 U2.6 23.64,33.85 ; 23.64,33.85 25.13,33.85 25.65,33.32 26.67,33.32 26.73,33.27 27.59,33.27 v1(27.81,33.05)
  BOTTOM w0.203: R5.2 37.57,42.7 36.78,41.91 31.95,41.91 29.01,38.96 29.01,34.24 v1(27.81,33.05)
FAULT_LED2: length 20.1
  TOP w0.203: v1(26.8,32.53) 26.68,32.53 26.49,32.72 25.5,32.72 24.92,33.3 24.48,33.3 24.23,33.05 23.64,33.05
  BOTTOM w0.203: R6.2 37.57,40.77 36.75,39.95 32.23,39.95 29.49,37.21 29.49,33.65 28.27,32.44 26.9,32.44 v1(26.8,32.53)
FAULT_LED3: length 18.5
  TOP w0.203: v1(26.9,31.78) 24.71,31.78 24.23,32.25 23.64,32.25
  BOTTOM w0.203: v1(26.9,31.78) 28.27,31.78 30.05,33.55 30.05,35.81 32.26,38.02 36.75,38.02 37.57,38.84 R7.2
FAULT_LED4: length 17.8
  TOP w0.203: 23.64,31.85 24.03,31.85 24.92,30.96 v1(26.87,30.96)
  BOTTOM w0.203: R8.2 37.57,36.96 36.75,36.14 31.85,36.14 30.94,35.23 30.94,33.67 28.23,30.96 v1(26.87,30.96)
FAULT_LED5: length 29.8
  TOP w0.203: U2.50 15.73,32.25 15.09,32.25 14.27,31.43 v1(14.27,30.73)
  BOTTOM w0.203: v1(14.27,30.73) 14.27,29.96 15.43,28.8 26.72,28.8 31.93,34.01 34.67,34.01 34.7,33.99 36.47,33.99 37.57,35.08 R9.2
FAULT_LED6: length 31.2
  TOP w0.203: v1(13.28,30.72) 13.28,30.89 13.89,31.5 13.89,31.59 14.94,32.63 15.03,32.63 15.05,32.65 15.73,32.65 U2.49
  BOTTOM w0.203: v1(13.28,30.72) 13.28,30.02 14.96,28.35 27.41,28.35 31.37,32.31 36.73,32.31 37.57,33.15 R10.2
FAULT_LED7: length 32.9
  TOP w0.203: v1(12.27,30.71) 12.84,31.28 13.04,31.28 14.78,33.01 14.8,33.01 14.84,33.05 U2.48
  BOTTOM w0.203: R11.2 37.57,31.22 36.65,30.3 30.99,30.3 28.57,27.89 14.38,27.89 12.27,30 v1(12.27,30.71)
FAULT_LED8: length 34.9
  TOP w0.203: v1(11.23,30.71) 11.23,30.91 12.09,31.78 12.95,31.78 14.63,33.45 15.73,33.45 U2.47
  BOTTOM w0.203: v1(11.23,30.71) 11.23,29.92 13.77,27.38 29.67,27.38 30.84,28.55 36.75,28.55 37.57,29.36 R12.2
FAULT_LED9: length 37.3
  TOP w0.203: v1(10.13,30.71) 10.13,31.24 11.99,33.1 13.2,33.1 14.35,34.25 15.73,34.25 U2.45
  BOTTOM w0.203: R13.2 37.57,27.51 36.7,26.64 13.59,26.64 10.13,30.1 v1(10.13,30.71)
MCU_CMD: length 47.2
  TOP w0.203: 23.64,35.85 24.83,35.85 28.99,40 41.61,40 46.69,34.92 63.02,34.92 64.03,35.94 J11.9
MCU_CSB: length 57.7
  TOP w0.203: 23.64,36.25 24.67,36.25 25.2,36.78 25.2,36.86 30.14,41.81 42.09,41.81 46.94,36.96 65.85,36.96 66.06,37.17 67.14,37.17 67.82,37.85 67.82,44.86 J11.1
MCU_ENABLE: length 61.3
  TOP w0.203: U2.51 15.74,30.72 15.59,30.58 15.59,23.3 16.36,22.53 48.21,22.53 50.44,24.77 63.02,24.77 64.03,25.78 J11.17
MCU_NFAULT: length 51.6
  TOP w0.203: 23.64,34.25 25.27,34.25 25.66,33.86 28.32,33.86 31.72,30.45 v1(40.84,30.45) 44.86,30.45 46.48,28.83 63.53,28.83 64.03,28.32 66.57,28.32
  BOTTOM w0.203: v1(40.84,30.45) 40.84,28.93 R15.2
MCU_SCK: length 47.5
  TOP w0.203: J11.3 64.03,43.56 63.53,43.05 45.75,43.05 43.64,45.16 31.45,45.16 24.87,38.58 24.87,38.36 24.82,38.31 24.82,38.2 24.43,37.82 24.43,37.72 24.17,37.45 23.64,37.45
MCU_SDI: length 47.6
  TOP w0.203: 23.64,37.05 24.29,37.05 24.31,37.07 24.33,37.07 24.82,37.56 24.82,37.67 25.2,38.05 25.2,38.15 31.59,44.55 43.6,44.55 47.13,41.02 J11.5
MCU_SDO: length 48.3
  TOP w0.203: 66.57,38.48 64.03,38.48 63.53,38.99 47.19,38.99 42.27,43.92 31.61,43.92 25.2,37.51 25.2,37.4 24.82,37.02 24.82,36.94 24.57,36.69 24.47,36.69 24.43,36.65 23.64,36.65
MCU_TRIGA: length 46.3
  TOP w0.203: J11.11 64.03,33.4 63.53,32.89 46.56,32.89 41.53,37.92 27.55,37.92 25.84,36.21 25.82,36.21 25.05,35.45 23.64,35.45
MCU_TRIGB: length 45.6
  TOP w0.203: 23.64,35.05 25.19,35.05 25.74,35.6 25.96,35.6 26.54,36.17 40.77,36.17 46.08,30.86 66.57,30.86
PMIC_SCL: length 23.8
  TOP w0.203: U3.D1 16.8,50.31 18.14,50.31 v1(18.92,49.53) ; U2.54 v1(17.28,29.98)
  BOTTOM w0.203: v1(18.92,49.53) 18.92,49.43 18.87,49.37 18.87,48.54 18.06,47.74 18.03,47.74 18.03,39.62 17.75,39.34 17.75,30.45 v1(17.28,29.98)
PMIC_SDA: length 25.3
  TOP w0.203: U3.C1 17.78,49.91 v1(18.16,49.53) ; U2.55 17.69,31.1 17.69,30.45 v1(18.16,29.97)
  BOTTOM w0.203: v1(18.16,49.53) 18.16,49.63 18.67,50.14 19.18,50.14 19.56,49.76 19.56,48.77 19.32,48.53 19.32,48.35 18.8,47.83 18.8,38.73 19.05,38.48 19.05,30.86 v1(18.16,29.97)
SRST: length 8.4
  TOP w0.203: J2.10 v1(22.86,44.58) ; U2.22 21.28,39.49 21.31,39.51 21.31,39.6 21.45,39.74 v1(21.45,41.02)
  BOTTOM w0.203: v1(22.86,44.58) 21.45,43.16 v1(21.45,41.02)
SWOUT: length 38.1
  TOP w0.203: 14.1,50.16 13.84,50.16 ; U2.46 15.73,33.85 14.56,33.85 14.54,33.83 14.47,33.83 13.33,32.69 12.87,32.69 v1(12.67,32.5) ; 14.12,50.16 14.35,50.16 14.61,49.91 U3.C5 ; U2.19 22.49,39 22.49,39.88
  TOP w0.229: 14.12,50.16 14.1,50.16
  TOP w0.508: 13.84,50.16 v1(13.34,50.16) C6.2 ; 22.49,39.88 22.49,41.27 21.73,42.02 19.15,42.02 18.77,41.64 14.37,41.64 v1(14.29,41.72)
  BOTTOM w0.508: v1(12.67,32.5) 12.96,32.5 15.49,35.03 15.49,35.24 15.54,35.29 15.54,36.94 15.56,36.96 15.56,37.59 15.49,37.65 15.49,40.51 v1(14.29,41.72) 12.45,43.56 12.45,49.28 v1(13.34,50.16)
UNNAMED_1_CAPNP_I58_1: length 2.5
  TOP w0.254: U1.22 95.19,36.31 95.35,36.47 C21.1
UNNAMED_1_CAPNP_I58_2: length 2.8
  TOP w0.254: U1.23 94.65,36.81 95.53,37.69 C21.2
UNNAMED_1_CAPNP_I62_2: length 2.7
  TOP w0.203: U1.20 95.41,35.31 95.49,35.23 95.99,35.23 C19.2
UNNAMED_1_CAPNP_I64_1: length 4.3
  TOP w0.254: C20.1 95.99,38.79 95.4,38.2 95.32,38.2 94.43,37.31 U1.24
UNNAMED_1_EKHEADER2P_I105_1: length 4.4
  TOP w0.203: R17.1 R18.2 97.94,31.19 100.25,31.19 J16.1
UNNAMED_1_EKMAX22200_I140_18: length 3
  TOP w0.203: R17.2 94.87,34.06 94.62,34.06 94.37,34.31 U1.18
UNNAMED_1_EKMAX22200_I141_10: length 28.4
  TOP w0.305: v1(89.92,32.26) 89.92,32.33 90.06,32.48 90.06,33.14 U1.10
  BOTTOM w0.508: J12.4 112,33.35 108.69,33.35 104.8,29.46 98.86,29.46 95.86,32.46 95.86,32.48 94.97,33.38 90.63,33.38 89.92,32.66 v1(89.92,32.26)
UNNAMED_1_EKMAX22200_I141_11: length 27
  TOP w0.305: v1(90.7,32.26) 90.56,32.4 90.56,33.14 U1.11
  BOTTOM w0.508: v1(90.7,32.26) 91.06,32.61 94.65,32.61 95.1,32.17 95.1,32.15 98.54,28.7 105.12,28.7 109,32.59 112.22,32.59 J12.3
UNNAMED_1_EKMAX22200_I141_14: length 26.2
  TOP w0.305: v1(91.97,31.24) 91.97,32.26 92.06,32.35 92.06,33.14 U1.14
  BOTTOM w0.508: v1(91.97,31.24) 91.97,31.38 92.42,31.83 93.25,31.83 98.03,27.05 108.13,27.05 109.35,28.27 112,28.27 J12.2
UNNAMED_1_EKMAX22200_I141_15: length 25.3
  TOP w0.305: v1(92.74,31.06) 92.74,31.62 92.71,31.65 92.71,32.26 92.56,32.41 92.56,33.14 U1.15
  BOTTOM w0.508: v1(92.74,31.06) 92.75,31.05 92.95,31.05 97.82,26.19 108.38,26.19 109.7,27.51 112.22,27.51 J12.1
UNNAMED_1_EKMAX22200_I141_26: length 24.8
  TOP w0.305: v1(92.71,38.86) 92.56,38.71 92.56,37.98 U1.26
  BOTTOM w0.508: J12.5 112.28,37.62 109.34,37.62 104.79,42.16 96.01,42.16 v1(92.71,38.86)
UNNAMED_1_EKMAX22200_I141_27: length 26.2
  TOP w0.305: v1(91.95,38.91) 91.95,38.91 91.95,38.9 92.06,38.79 92.06,37.98 U1.27
  BOTTOM w0.508: J12.6 111.95,38.38 109.65,38.38 105.11,42.93 95.68,42.93 91.95,39.19 v1(91.95,38.91)
UNNAMED_1_EKMAX22200_I141_30: length 29.6
  TOP w0.254: v1(90.71,38.86) 90.56,38.71 90.56,37.98 U1.30
  BOTTOM w0.508: J12.7 112.35,42.62 110.3,42.62 107.71,45.21 92.96,45.21 90.71,42.96 v1(90.71,38.86)
UNNAMED_1_EKMAX22200_I141_31: length 31.1
  TOP w0.305: U1.31 90.06,37.98 90.06,38.75 v1(89.95,38.86)
  BOTTOM w0.508: J12.8 111.88,43.38 110.62,43.38 108.03,45.97 92.52,45.97 89.95,43.4 v1(89.95,38.86)
UNNAMED_1_LED_I106_B: length 1.6
  TOP w0.203: D13.C R20.1
UNNAMED_4_B3U-1000PX_I48_1: length 4.8
  TOP w0.203: SW1.1 17.02,28.87 17.48,29.34 18.77,29.34 19.68,30.26 U2.60
UNNAMED_4_CAPNP_I15_2: length 2.3
  TOP w0.203: U3.E5 U3.E4 15.6,50.31 U3.D4 U3.C4 U3.B4 ; U3.A1 v1(17.5,49.11)
  vias: v1(14.48,55.24) v1(15.37,51.18) v1(15.49,55.24)
UNNAMED_4_CAPNP_I35_1: length 3.2
  TOP w0.203: 14.27,50.88 14.84,50.31 15.2,50.31 U3.D5
  TOP w0.508: 14.27,50.88 13.84,51.31 C7.1
UNNAMED_4_INDUCT_I43_1: length 3.1
  TOP w0.203: U3.E2 16.4,51.58 16.64,51.82 16.64,52.89 L2.1
UNNAMED_4_INDUCT_I43_2: length 3
  TOP w0.203: L2.2 15.3,53.41 15.88,52.83 15.88,51.94 16,51.82 U3.E3
UNNAMED_4_INDUCT_I44_1: length 3.1
  TOP w0.203: L1.1 17.01,48.27 16.4,48.88 U3.A2
UNNAMED_4_LED4P_I4_KB: length 4.1
  TOP w0.203: R2.2 v1(20.45,26.04) ; v1(19.34,24.09) D12.3
  BOTTOM w0.203: v1(19.34,24.09) 20.45,25.19 v1(20.45,26.04)
UNNAMED_4_LED4P_I4_KG: length 2.8
  TOP w0.203: D12.4 19.44,24.94 19.18,25.2 R3.2
UNNAMED_4_LED4P_I4_KR: length 4.4
  TOP w0.203: R1.2 22.24,26.55 22.24,24.43 21.9,24.09 D12.2
UNNAMED_4_LED_I50_B: length 2.2
  TOP w0.508: D1.C v1(35.03,42.8)
  BOTTOM w0.508: v1(35.03,42.8) R5.1
UNNAMED_4_LED_I52_B: length 2.2
  TOP w0.508: D2.C v1(35.03,40.89)
  BOTTOM w0.508: v1(35.03,40.89) R6.1
UNNAMED_4_LED_I55_B: length 2.2
  TOP w0.508: D3.C v1(35.03,38.99)
  BOTTOM w0.508: v1(35.03,38.99) R7.1
UNNAMED_4_LED_I57_B: length 2.2
  TOP w0.508: D4.C v1(35.03,37.08)
  BOTTOM w0.508: v1(35.03,37.08) R8.1
UNNAMED_4_LED_I59_B: length 2.2
  TOP w0.508: D5.C v1(35.03,35.18)
  BOTTOM w0.508: v1(35.03,35.18) R9.1
UNNAMED_4_LED_I61_B: length 2.2
  TOP w0.508: D6.C v1(35.03,33.27)
  BOTTOM w0.508: v1(35.03,33.27) R10.1
UNNAMED_4_LED_I63_B: length 2.2
  TOP w0.508: D7.C v1(35.03,31.37)
  BOTTOM w0.508: v1(35.03,31.37) R11.1
UNNAMED_4_LED_I65_B: length 2.2
  TOP w0.508: D8.C v1(35.03,29.46)
  BOTTOM w0.508: v1(35.03,29.46) R12.1
UNNAMED_4_LED_I66_B: length 2.2
  TOP w0.508: D9.C v1(35.03,27.56)
  BOTTOM w0.508: v1(35.03,27.56) R13.1
UNNAMED_4_LED_I70_B: length 2.2
  TOP w0.508: D10.C v1(35.03,25.65)
  BOTTOM w0.508: v1(35.03,25.65) R15.1
UNNAMED_4_MAX32625_I78_32KIN: length 3.7
  TOP w0.203: U2.35 15.73,38.25 15.25,38.25 14.69,38.81 13.13,38.81 12.63,39.31 X1.2
UNNAMED_4_MAX32625_I78_32KOUT: length 3.7
  TOP w0.203: U2.36 15.73,37.85 15.11,37.85 14.61,38.35 13.08,38.35 12.63,37.91 X1.1
UNNAMED_4_MAX32625_I78_P2: length 3
  TOP w0.203: R1.1 21.72,29.65 21.28,30.08 U2.64
UNNAMED_4_MAX32625_I78_P2_1: length 2.8
  TOP w0.203: U2.62 20.49,29.59 20.45,29.55 R2.1
UNNAMED_4_MAX32625_I78_P2_2: length 3.2
  TOP w0.203: R3.1 19.18,29.21 20.09,30.12 20.09,31.1 U2.61
USB_DM: length 34.9
  TOP w0.201: J1.2 v1(5.46,55.26) ; v1(12.45,33.66) 12.6,33.81 13.37,33.81
  TOP w0.203: U2.44 15.72,34.63 15.58,34.63 14.27,34.63 14.26,34.63 14.19,34.63 13.37,33.81
  BOTTOM w0.201: v1(5.46,55.26) 5.31,55.11 4.61,55.11 4.17,54.67 4.17,35.27 5.6,33.83 12.27,33.83 v1(12.45,33.66)
USB_DP: length 33.6
  TOP w0.201: v1(12.45,34.42) 12.59,34.27 13.26,34.27 ; J1.3 5.35,54.61 v1(5.46,54.5)
  TOP w0.203: 13.26,34.27 14.04,35.05 15.01,35.05 15.01,35.05 U2.43
  BOTTOM w0.201: v1(5.46,54.5) 5.31,54.65 5.21,54.65 5.16,54.7 4.77,54.7 4.57,54.5 4.57,35.43 5.77,34.24 12.27,34.24 v1(12.45,34.42)
VM: length 10.4
  TOP w0.203: 91.31,37.97 91.31,37.98 91.31,39.62 ; 91.31,37.97 U1.29 ; 91.31,37.97 U1.28 ; 89.28,31.75 89.28,32.41 89.56,32.7 89.56,33.14 U1.9 ; U1.16 93.06,33.14 93.06,32.7 93.34,32.41 93.34,31.88 ; 89.28,38.74 89.56,38.46 89.56,37.98 U1.32 ; U1.12 91.31,33.15 ; 91.31,33.15 91.31,33.14 91.31,31.5 ; 91.31,33.15 U1.13 ; 93.47,39.5 93.47,38.83 93.06,38.42 93.06,37.98 U1.25
  TOP w0.254: 88.95,37.97 88.95,37.98 89.56,37.98
  vias: v1(87.38,40.51) v1(87.38,39.5) v1(88.14,40.51) v1(88.14,39.5) v1(88.14,38.48) v1(88.14,32.39) v1(88.14,31.37) v1(88.14,30.35) v1(88.9,40.51) v1(88.9,39.5) v1(88.9,32.39) v1(88.9,31.37) v1(88.9,30.35) v1(89.03,38.48) v1(89.66,31.37) v1(89.66,30.35) v1(90.65,31.17) v1(91.64,40.06) v1(92.2,40.64) v1(94.31,31.85) v1(94.74,39.24) v1(99.44,59.66) v1(99.44,56.87) v1(100.33,59.66) v1(100.33,56.87) v1(101.22,59.66) v1(101.22,56.87) v1(102.11,59.66) v1(102.11,56.87)

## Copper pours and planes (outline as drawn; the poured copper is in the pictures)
1.8V on TOP: 15.49,48.51 15.49,48.39 14.86,47.75 14.86,43.31 14.99,43.18 15.62,43.18 15.75,43.31 15.75,47.62 16.1,47.98 16.1,48.51
1.8V on PWR3: 14.61,43.56 14.61,28.32 15.49,27.43 28.57,27.43 29.59,28.45 29.59,43.81 29.46,43.81 29.46,52.96 29.4,53.02 29.4,58.86 28.96,59.31 21.97,59.31 21.59,58.93 21.59,44.58 20.83,43.81 14.86,43.81
3.3V on TOP: 19.05,51.05 19.05,51.82 17.53,51.82 16.89,51.18 17.27,50.8 17.53,51.05
3.3V on PWR3: 14.35,50.55 2.41,50.55 1.52,49.66 1.52,10.92 2.03,10.41 42.16,10.41 43.43,11.68 43.43,57.4 41.53,59.31 21.72,59.31 21.21,58.8 21.21,53.34 20.32,52.45 18.8,52.45 18.41,52.07 18.41,51.82 17.21,50.61 14.41,50.61
GND_SIGNAL on TOP: 91.06,27.94 91.06,29.46 92.79,29.46 92.79,27.94
GND_SIGNAL on TOP: 93.98,60.01 93.98,56.32 97.54,56.32 97.54,60.01
GND_SIGNAL on TOP: 91.03,41.5 91.03,43.03 92.76,43.03 92.76,41.5
GND_SIGNAL on BOTTOM: 62.74,69.72 115.54,69.72 115.54,1.52 62.74,1.52 ; 11 cut-outs
GND_SIGNAL on GND2: 0.76,70.36 115.57,70.36 115.57,0.76 0.76,0.76 ; 9 cut-outs
GND_SIGNAL on PWR3: 89.66,32.51 98.7,32.51 98.7,38.61 89.66,38.61
UNNAMED_4_10118193-0001LF_I7_1 on TOP: 4.83,56.64 4.83,58.8 8.89,58.8 8.89,55.75 3.56,55.75 3.56,56.64
UNNAMED_4_CAPNP_I15_2 on TOP: 14.1,54.86 14.1,56.01 11.05,56.01 11.05,58.8 15.75,58.8 15.75,58.29 15.71,58.29 15.71,57.53 15.75,57.53 15.75,56.52 15.71,56.52 15.71,55.75 15.75,55.75 15.75,54.86
UNNAMED_4_CAPNP_I15_2 on PWR3: 14.35,51.56 14.86,51.05 14.86,45.09 15.49,44.45 20.19,44.45 20.95,45.21 20.95,58.8 20.19,59.56 10.29,59.56 9.78,59.05 9.78,52.45 10.67,51.56
UNNAMED_4_INDUCT_I44_1 on TOP: 17.4,45.47 17.4,48.13 16.89,48.64 16.64,48.64 16.51,48.51 16.51,48.39 16.64,48.26 16.64,45.47
VM on TOP: 99,60.01 99,56.32 102.43,56.32 102.43,60.01
VM on TOP: 87.12,41.15 95.12,41.15 95.12,39.07 93.83,37.77 92.66,37.77 92.66,37.8 88.42,37.8 88.42,37.82 87.12,39.12
VM on TOP: 94.59,32.07 95.31,32.07 95.31,29.91 87.31,29.91 87.31,32.07 88.65,33.4 93.26,33.4
VM on PWR3: 63.5,69.98 63.5,10.16 115.57,10.16 115.57,69.98 ; 9 cut-outs

Small or netless copper shapes (teardrops, artwork), in the pictures only: 2 on TOP

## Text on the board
Ref Des/Silkscreen Top: OVER CURRENT PROTECTION DETECTED | MAX22200 IS ENABLED | OPEN LOAD FAULT | PLUNGER MOVEMENT FAULT | COMMUNICATION ERROR FAULT | UNDER VOLTAGE LOCKOUT FAULT | CHANNEL IS TRANSMITTING | FAULT DETECTED | THERMAL EVENT DETECTED | HIT CURRENT NOT REACHED FAULT | SDO | TRIGA | CSB | SCK | SDI | CMD | ENABLE | TRIGB | NFAULT | GND | OUTPUT 0 | OUTPUT 1 | OUTPUT 3 | OUTPUT 5 | OUTPUT 2 | OUTPUT 4 | OUTPUT 6 | OUTPUT 7 | VM | SRST | DBG_RX | DBG_TX | DBG_SWC | DBG_SWD | 3.3V | MAX22200_EVKIT_A
User.21: SCAN FOR INFO | KEEP CENTER OF STANDOFF HOLES 0.2" AWAY FROM BOARD EDGES | USE FOR ONLY 1 MAXIM PART OPTION | USE FOR MULTI MAXIM PART OPTIONS | MAXyyyyy_EVKIT_P1 | MAXzzzzz_EVKIT_P1 | THE PLASTIC PRESS-IN STANDOFF (4-PLCS). | DEFAULT MOUNTING HOLE IS FOR | MAXINV# XXXXXX | DEFAULT LOCATION FOR HARDWARE NAME | ADD TEXT UNDER QR CODE | MUST READ "SCAN FOR INFO" | DEFAULT QR CODE LOCATION | DEFAULT LOGO LOCATION | EVKIT NAMING OPTIONS | (HARDWARE NAME ONLY)
User.23: NOTES: | SURFACE FINISH: | TESTING: | SOLDERMASK: | MISCELLANEOUS: | SILKSCREEN: | MATERIAL: | TOOLING: | 16.  VENDOR LOGO & DATE CODE REQUIREMENT.  DATE CODE FORMAT MUST BE YYWW ONLY | 17.  FINAL ELECTRICAL TEST TO BE PERFORMED USING PROVIDED IPC-D-356A NETLIST OR ODB++ FORMAT FILE. | 18.  A TIME DOMAIN REFLECTOMETER REPORT FOR EACH IMPEDANCE CONTROLLED LAYER AND A CERTIFICATE | 19. IF PRESENT, ALL BLIND/BURIED VIAS WITH AN ASPECT RATIO <1:1 TO BE PLATED SHUT WITH COPPER WHEN | 20.  FOR ALL DRILL INFORMATION REFER TO DRILL CHART. | 21.  FINISHED SURFACE CONTACTS AND FILLED VIAS TO BE FREE OF ANY PITS. SCRATCHES PROBE MARKS | 23.  PEMNUT | 14.  SOLDERMASK OVER BARE COPPER OR BARE GOLD (BOTH SIDES) WITH LIQUID PHOTO IMAGEABLE (LPI) INK | 13.  DRILL SIZES ARE FINISHED HOLE SIZES. ALL HOLES SHALL BE LOCATED WITHIN .005 DTP. | 22.  THIEVING: | 9.  ALL TRACES FILLETED OPTION TO ENHANCE RELIABILITY AT PAD JUNCTIONS | 10.  LAYER TO LAYER REGISTRATIONS SHALL BE WITHIN .003 INCHES. | 15. APPLY SILKSCREEN USING A NON-CONDUCTIVE EPOXY INK | 11.  FINISHED COPPER WEIGHT/THICKNESS: | 12. USE CHECKED ITEMS FOR PLATING | 3.  THE PCB SHALL BE FABRICATED TO IPC-6012, TYPE X, CLASS 2. | 4.  BOARD MATERIAL & CONSTRUCTION SHALL MEET THE REQUIREMENTS OF UL796 | 5.  OVERALL BOARD THICKNESS REFER TO LAMINATION DIAGRAM. TOLERANCE APPLIES | 6.  BOW & TWIST NOT TO EXCEED 0.0075 IN. (0.75%) PER LINEAR INCH. | 7.  PHOTO ETCH CIRCUITRY PER ENCLOSED GERBER RS274X OR ODB++ FORMAT FILE. | 8.  IMPEDANCE REQUIREMENTS: IF NO STACKUP IS DEFINED, THE VENDOR IS ALLOWED TO ADJUST THE DIELECTRIC | 1.  DIMENSIONS ARE IN INCHES (EXCEPT WHERE NOTED). | 2.  BOARD MATERIAL: | (X)  FINISH CONDUCTOR SURFACES: IMMERSION GOLD, 2-5 MICRO INCHES OVER | (X)  WHITE | ( )  OTHER ________________________ | ( )  FINGERS TO BE GOLD PLATED. | ( )  LEAD FREE AND RoHS COMPLIANT PLATING (OSP NOT INCLUDED) | (X)  REFER TO LAMINATION DIAGRAM FOR FINISHED COPPER WEIGHT/THICKNESS REQUIREMENTS. | (X)  PLACE ON BOTTOM LEGEND LAYER. IF NO BOTTOM LEGEND SUPPLIED, CREATE BOTTOM LEGEND LAYER TO ADD. | ( )  PLACE ON TOP LEGEND LAYER. IF NO TOP LEGEND SUPPLIED,CREATE TOP LEGEND LAYER TO ADD. | ( )  ELECTRODEPOSITED HARD GOLD PLATE, TYPE 1 (99.7% MIN GOLD), GRADE C | (X)  CUSTOM MAXIM TEAL SOLDER MASK. PANTONE #326C. | MINIMUM BARREL PLATING OF .001 IN. PLATED HOLES SHALL NOT BE ROUGH OR IRREGULAR SO AS TO | HINDER PROPER SOLDER WICKING. BARREL RELIEF ON SOLDERMASK ALLOWED ON UNFILLED VIA IN PAD HOLES. | USED AS VIA-IN PAD OR AS A STACKED VIA. BLIND/BURIED VIAS WITH AN ASPECT RATIO >1:1 TO BE FILLED | WITH NON-CONDUCTIVE EPOXY. UNLESS OTHERWISE SPECIFIED. | (x)  NON-CONDUCTIVE EPOXY. FILL AND CAP ALL 0.004 INCH DRILLED VIAS. | ( )  SILVER. FILL AND CAP ALL 0.XXXX INCH DRILLED VIAS. | (REQUIRED UNLESS OTHERWISE SPECIFIED IN QUOTE) | THE PCB SHALL HAVE A VERIFICATION STAMP. | OR OTHER DEFORMITIES THAT COULD EFFECT THE APPERANCE AND PERFORMACE OF THE CONTACT | SURFACE. CONTACTS ARE TO BE AS FLAT AS POSSIBLE. NOT TO EXCEED +/- 0.001" OF FLATNESS. | OF COMPLIANCE SHALL BE PROVIDED BY VENDOR AT TIME OF SHIPMENT. INSTANCES WHERE TDR TESTING | CAN'T BE PERFORMED BECAUSE THE TRACE LENGTH IS TOO SHORT ON THE OUTER LAYERS AT THE PIN ESCAPES | IS ACCEPTABLE, ALL OTHER INSTANCES MUST BE REPORTED. | ( )  SUPPLIER MAY ADD THIEVING TO COMPENSATE FOR LOW COPPER DENSITY AREAS ON THIS DESIGN. | WHERE SPACING PERMITS. | LEGEND TO LEGEND +/- 0.007 INCHES | (X)  SUPPLIER MAY NOT ADD THIEVING TO COMPENSATE FOR LOW COPPER DENSITY AREAS ON THIS DESIGN. | ( )  PEMNUTS TO BE INSTALLED BY FABRICATOR.. | ( )  PEMNUTS NOT TO BE INSTALLED BY FABRICATOR. | (X)  NOT APPLICABLE. | ( )  FILLETED | (X)  NOT FILLETED | (X)  ISOLA 370HR OR EQUIVALENT | ( )  NELCO-4000-13 | ( )  MEGTRON 6 | ( )  ROGERS 4350B | ( )  ROGERS 4003C | ( )  ISOLA-FR408HR OR EQUIVALENT | WORKMANSHIP SHALL CONFORM TO IPC-A-600, CLASS 2, CURRENT REVISIONS. | WITH FLAMMABILITY RATING OF 94V-O. | AFTER ALL LAMINATION AND PLATING PROCESSES. IT IS TO BE MEASURED FROM | TOP PCB METAL TO BOTTOM PCB METAL UNLESS OTHERWISE SPECIFIED. | BOW & TWIST SHOULD BE MEASURED PER IPC-TM-650, METHOD 2.4.22. | DRILL LOCATION AND SIZE CONTROLLED BY EXCELLON CNC DRILL FILE. | THICKNESS AND TRACE WIDTHS TO MEET THE IMPEDANCE REQUIREMENT. IF SPECIFIED, VENDOR MUST FOLLOW AND | MEET THE REQUIREMENTS LISTED IN THE IMPEDANCE TABLE. ANY ADJUSTMENTS MADE TO THE DEFINED STACKUP, | TRACE WIDTH & SPACING THAT IMPACT THE REQUIREMENTS MUST HAVE WRITTEN APPROVAL FROM MAXIM. | UNLESS OTHERWISE SPECIFIED | (USE CHECKED ITEMS FOR MATERIAL) | (KNOOP HARDNESS 130-200), CLASS 1 (50-100 MICRO INCHES THICK) IN ACCORDANCE WITH MIL-G-45204C. | GENERAL SURFACING REQUIREMENTS MUST MEET ANSI/IPC-A-600(CURRENT REV) SECTION 4.0, | CLASS 3 (50-100 MICROINCHES THICK) OVER ELECTRODEPOSITED NICKEL PLATE | IN ACCORDANCE WITH ANSI/IPC-A-600D, SECTION 4.0, CLASS 3 (200-600 MICROINCHES THICK). | 118-236 MICRO INCHES MINIMUM OF ELECTROLESS NICKEL. | THE STARTING COPPER WEIGHT/THICKNESS CAN VARY AS LONG AS THE FINISHED COPPER | WEIGHT/THICKNESS IS NOT LESS THAN THE SPECIFIED VALUE, UNLESS OTHERWISE SPECIFIED. | UNLESS OTHERWISE SPECIFIED: | MAX22200_EVKIT_A
User.45: FIGURE | SIZE | 4.0 | 10.0 | 36.0 | 43.3071 | 45.28 | 51.1811 | 62.9921 | 125.0 | 47.24x19.69 | TOLERANCE | +0.0/-4.0 | +3.0/-8.0 | +3.0/-3.0 | PLATED | ALL UNITS ARE IN MILS | QTY | 6 | 180 | 2 | 20 | 16 | 7 | 8 | NOTES | DRILL CHART: TOP to BOTTOM
